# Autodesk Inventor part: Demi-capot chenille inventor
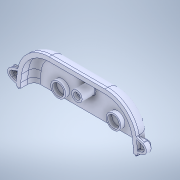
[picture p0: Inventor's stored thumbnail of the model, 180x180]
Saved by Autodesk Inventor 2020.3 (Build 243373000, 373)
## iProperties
Created: 2018-09
Part Number: Demi-capot chenille inventor
Material: Générique
Document SubType Name: Modeling
Designer: ficho
Density: 1 g/cm^3
Appearance: Par défaut
Mass: 16.931 g
Surface Area: 163.992 cm^2
Volume: 16.931 cm^3
Sending System: SolidWorks 2015
Last Author: adrien
Last Saved: 2019-01-10
Author: ficho
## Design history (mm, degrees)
feature "Enlèv. mat.-Extru.15"
sketch "Esquisse1"
  geometry: C1 r 7 at (21.5, 8.1) reference; C2 r 5.5 at (21.5, 8.1) reference; 1 further point
extrude "Extrusion1" cut sketch "Esquisse1" extent not by distance; stored distance "d0" = 12.74; taper "d1" = 0 deg
sketch "Esquisse2"
  geometry: C1 r 5.5 at (73.5, 8.1) reference; C2 r 7 at (73.5, 8.1) reference; C3 r 5.505 at (21, 8.1); C4 r 7.048 at (21, 8.1); 1 further point
  constraints: 2 centre point, 1 coincident
  dimensions: "d2" = 52.5 distance of C3.centre C1.centre
extrude "Extrusion2" join sketch "Esquisse2" stored distance "d3" = 10; taper "d4" = 0 deg
node "Solide1"
node "Boucle projetée1"
